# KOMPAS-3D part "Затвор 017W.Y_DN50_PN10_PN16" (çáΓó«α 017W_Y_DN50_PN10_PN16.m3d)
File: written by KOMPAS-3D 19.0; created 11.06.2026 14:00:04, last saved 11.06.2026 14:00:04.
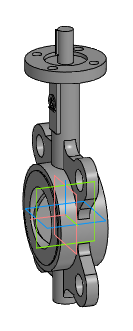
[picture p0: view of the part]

Document properties: Автор: Евгений; Полное имя файла: Z:\3.Личные\kachalov\001_3d для проектировщиков\x.x Тип 017W.Y(S) Затвор дисковый поворотный межфланцевый\_stp_Затвор 017W.Y_DN50-DN350\Затвор 017W_Y_DN50_PN10_PN16.m3d

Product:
- Part/product: Затвор 017W.Y_DN50_PN10_PN16

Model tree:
1. Операция без истории:1  (labels: Затвор 017W.Y_DN50_PN10_PN16)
